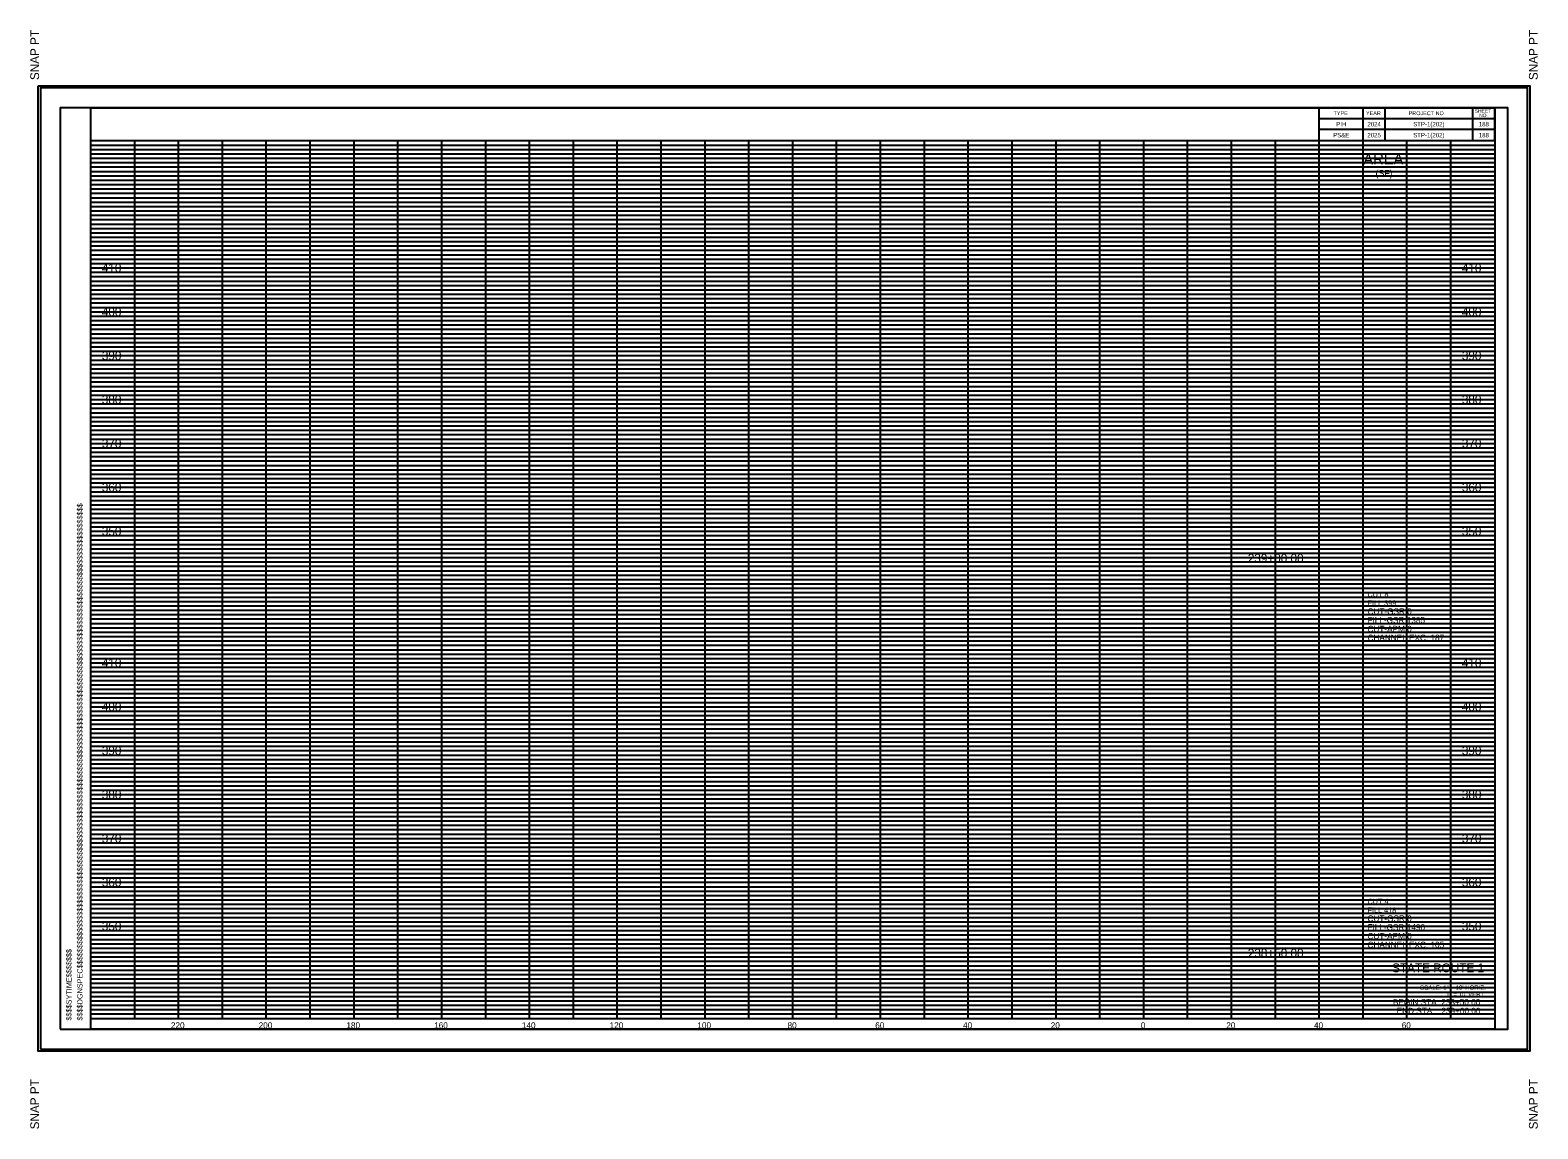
# Model space of a CAD drawing. Extents: x -200 to 23470, y -200 to 2389.
# Drawn here: x 11206.2 to 11549.8, y 974.8 to 1225.2 of the extents above; entities that cross this region are included whole.
import ezdxf

# ---------------------------------------------------------------- set-up
doc = ezdxf.new("R2010")
doc.units = 0
for name, color, linetype in [('Default', 7, 'Continuous'), ('DESIGN - SCRATCH - User 1', 7, 'Continuous'), ('DESIGN - SHEET - Corner Text', 7, 'Continuous'), ('DESIGN - SHEET - Light Grid', 7, 'Continuous'), ('DESIGN - SHEET - Linework', 7, 'Continuous'), ('DESIGN - SHEET - Plot Shape', 7, 'Continuous'), ('DESIGN - TYPICAL - Text', 7, 'Continuous')]:
    doc.layers.add(name, color=color, linetype=linetype)

# ---------------------------------------------------------------- blocks, each defined once
blk = doc.blocks.new('XSTSHT')
at = {"layer": 'DESIGN - SCRATCH - User 1'}
for p, q in [((28.5, 20.375), (28.5, 20.375)), ((29.25, 20.375), (29.25, 20.375)), ((30.5, 20.375), (30.5, 20.375)), ((31.75, 20.375), (31.75, 20.375)), ((28.5, 20.125), (28.5, 20.125)), ((29.25, 20.125), (29.25, 20.125)), ((30.5, 20.125), (30.5, 20.125)), ((31.75, 20.125), (31.75, 20.125)), ((0, 0), (0, 0))]:
    blk.add_line(p, q, dxfattribs=at)
at = {"layer": 'DESIGN - SHEET - Light Grid'}
for p, q in [((0, 19.9), (32, 19.9)), ((0, 19.8), (32, 19.8)), ((0, 19.7), (32, 19.7)), ((0, 19.6), (32, 19.6)), ((0, 19.5), (32, 19.5)), ((0, 19.4), (32, 19.4)), ((0, 19.3), (32, 19.3)), ((0, 19.2), (32, 19.2)), ((0, 19.1), (32, 19.1)), ((0, 18.9), (32, 18.9)), ((0, 18.8), (32, 18.8)), ((0, 18.7), (32, 18.7)), ((0, 18.6), (32, 18.6)), ((0, 18.5), (32, 18.5)), ((0, 18.4), (32, 18.4)), ((0, 18.3), (32, 18.3)), ((0, 18.2), (32, 18.2)), ((0, 18.1), (32, 18.1)), ((0, 17.9), (32, 17.9)), ((0, 17.8), (32, 17.8)), ((0, 17.7), (32, 17.7)), ((0, 17.6), (32, 17.6)), ((0, 17.5), (32, 17.5)), ((0, 17.4), (32, 17.4)), ((0, 17.3), (32, 17.3)), ((0, 17.2), (32, 17.2)), ((0, 17.1), (32, 17.1)), ((0, 16.9), (32, 16.9)), ((0, 16.8), (32, 16.8)), ((0, 16.7), (32, 16.7)), ((0, 16.6), (32, 16.6)), ((0, 16.5), (32, 16.5)), ((0, 16.4), (32, 16.4)), ((0, 16.3), (32, 16.3)), ((0, 16.2), (32, 16.2)), ((0, 16.1), (32, 16.1)), ((0, 15.9), (32, 15.9)), ((0, 15.8), (32, 15.8)), ((0, 15.7), (32, 15.7)), ((0, 15.6), (32, 15.6)), ((0, 15.5), (32, 15.5)), ((0, 15.4), (32, 15.4)), ((0, 15.3), (32, 15.3)), ((0, 15.2), (32, 15.2)), ((0, 15.1), (32, 15.1)), ((0, 14.9), (32, 14.9)), ((0, 14.8), (32, 14.8)), ((0, 14.7), (32, 14.7)), ((0, 14.6), (32, 14.6)), ((0, 14.5), (32, 14.5)), ((0, 14.4), (32, 14.4)), ((0, 14.3), (32, 14.3)), ((0, 14.2), (32, 14.2)), ((0, 14.1), (32, 14.1)), ((0, 13.9), (32, 13.9)), ((0, 13.8), (32, 13.8)), ((0, 13.7), (32, 13.7)), ((0, 13.6), (32, 13.6)), ((0, 13.5), (32, 13.5)), ((0, 13.4), (32, 13.4)), ((0, 13.3), (32, 13.3)), ((0, 13.2), (32, 13.2)), ((0, 13.1), (32, 13.1)), ((0, 12.9), (32, 12.9)), ((0, 12.8), (32, 12.8)), ((0, 12.7), (32, 12.7)), ((0, 12.6), (32, 12.6)), ((0, 12.5), (32, 12.5)), ((0, 12.4), (32, 12.4)), ((0, 12.3), (32, 12.3)), ((0, 12.2), (32, 12.2)), ((0, 12.1), (32, 12.1)), ((0, 11.9), (32, 11.9)), ((0, 11.8), (32, 11.8)), ((0, 11.7), (32, 11.7)), ((0, 11.6), (32, 11.6)), ((0, 11.5), (32, 11.5)), ((0, 11.4), (32, 11.4)), ((0, 11.3), (32, 11.3)), ((0, 11.2), (32, 11.2)), ((0, 11.1), (32, 11.1)), ((0, 10.9), (32, 10.9)), ((0, 10.8), (32, 10.8)), ((0, 10.7), (32, 10.7)), ((0, 10.6), (32, 10.6)), ((0, 10.5), (32, 10.5)), ((0, 10.4), (32, 10.4)), ((0, 10.3), (32, 10.3)), ((0, 10.2), (32, 10.2)), ((0, 10.1), (32, 10.1)), ((0, 9.9), (32, 9.9)), ((0, 9.8), (32, 9.8)), ((0, 9.7), (32, 9.7)), ((0, 9.6), (32, 9.6)), ((0, 9.5), (32, 9.5)), ((0, 9.4), (32, 9.4)), ((0, 9.3), (32, 9.3)), ((0, 9.2), (32, 9.2)), ((0, 9.1), (32, 9.1)), ((0, 8.9), (32, 8.9)), ((0, 8.8), (32, 8.8)), ((0, 8.7), (32, 8.7)), ((0, 8.6), (32, 8.6)), ((0, 8.5), (32, 8.5)), ((0, 8.4), (32, 8.4)), ((0, 8.3), (32, 8.3)), ((0, 8.2), (32, 8.2)), ((0, 8.1), (32, 8.1)), ((0, 7.9), (32, 7.9)), ((0, 7.8), (32, 7.8)), ((0, 7.7), (32, 7.7)), ((0, 7.6), (32, 7.6)), ((0, 7.5), (32, 7.5)), ((0, 7.4), (32, 7.4)), ((0, 7.3), (32, 7.3)), ((0, 7.2), (32, 7.2)), ((0, 7.1), (32, 7.1)), ((0, 6.9), (32, 6.9)), ((0, 6.8), (32, 6.8)), ((0, 6.7), (32, 6.7)), ((0, 6.6), (32, 6.6)), ((0, 6.5), (32, 6.5)), ((0, 6.4), (32, 6.4)), ((0, 6.3), (32, 6.3)), ((0, 6.2), (32, 6.2)), ((0, 6.1), (32, 6.1)), ((0, 5.9), (32, 5.9)), ((0, 5.8), (32, 5.8)), ((0, 5.7), (32, 5.7)), ((0, 5.6), (32, 5.6)), ((0, 5.5), (32, 5.5)), ((0, 5.4), (32, 5.4)), ((0, 5.3), (32, 5.3)), ((0, 5.2), (32, 5.2)), ((0, 5.1), (32, 5.1)), ((0, 4.9), (32, 4.9)), ((0, 4.8), (32, 4.8)), ((0, 4.7), (32, 4.7)), ((0, 4.6), (32, 4.6)), ((0, 4.5), (32, 4.5)), ((0, 4.4), (32, 4.4)), ((0, 4.3), (32, 4.3)), ((0, 4.2), (32, 4.2)), ((0, 4.1), (32, 4.1)), ((0, 3.9), (32, 3.9)), ((0, 3.8), (32, 3.8)), ((0, 3.7), (32, 3.7)), ((0, 3.6), (32, 3.6)), ((0, 3.5), (32, 3.5)), ((0, 3.4), (32, 3.4)), ((0, 3.3), (32, 3.3)), ((0, 3.2), (32, 3.2)), ((0, 3.1), (32, 3.1)), ((0, 2.9), (32, 2.9)), ((0, 2.8), (32, 2.8)), ((0, 2.7), (32, 2.7)), ((0, 2.6), (32, 2.6)), ((0, 2.5), (32, 2.5)), ((0, 2.4), (32, 2.4)), ((0, 2.3), (32, 2.3)), ((0, 2.2), (32, 2.2)), ((0, 2.1), (32, 2.1)), ((0, 1.9), (32, 1.9)), ((0, 1.8), (32, 1.8)), ((0, 1.7), (32, 1.7)), ((0, 1.6), (32, 1.6)), ((0, 1.5), (32, 1.5)), ((0, 1.4), (32, 1.4)), ((0, 1.3), (32, 1.3)), ((0, 1.2), (32, 1.2)), ((0, 1.1), (32, 1.1)), ((0, 0.9), (32, 0.9)), ((0, 0.8), (32, 0.8)), ((0, 0.7), (32, 0.7)), ((0, 0.6), (32, 0.6)), ((0, 0.5), (32, 0.5)), ((0, 0.4), (32, 0.4)), ((0, 0.3), (32, 0.3)), ((0, 0.2), (32, 0.2)), ((0, 0.1), (32, 0.1))]:
    blk.add_line(p, q, dxfattribs=at)
at = {"layer": 'DESIGN - SHEET - Linework'}
for p, q in [((32, 20.75), (28, 20.75)), ((28, 20), (28, 20.75)), ((29, 20), (29, 20.75)), ((29.5, 20), (29.5, 20.75)), ((31.5, 20), (31.5, 20.75)), ((32, 20), (32, 20.75)), ((32, 20.5), (28, 20.5)), ((0, 20), (32, 20)), ((1, 0), (1, 20)), ((2, 0), (2, 20)), ((3, 0), (3, 20)), ((4, 0), (4, 20)), ((5, 0), (5, 20)), ((6, 0), (6, 20)), ((7, 0), (7, 20)), ((8, 0), (8, 20)), ((9, 0), (9, 20)), ((10, 0), (10, 20)), ((11, 0), (11, 20)), ((12, 0), (12, 20)), ((13, 0), (13, 20)), ((14, 0), (14, 20)), ((15, 0), (15, 20)), ((16, 0), (16, 20)), ((17, 0), (17, 20)), ((18, 0), (18, 20)), ((19, 0), (19, 20)), ((20, 0), (20, 20)), ((21, 0), (21, 20)), ((22, 0), (22, 20)), ((23, 0), (23, 20)), ((24, 0), (24, 20)), ((25, 0), (25, 20)), ((26, 0), (26, 20)), ((27, 0), (27, 20)), ((32, 20.25), (28, 20.25)), ((28, 0), (28, 20)), ((29, 0), (29, 20)), ((30, 0), (30, 20)), ((31, 0), (31, 20)), ((0, 19), (32, 19)), ((0, 18), (32, 18)), ((0, 17), (32, 17)), ((0, 16), (32, 16)), ((0, 15), (32, 15)), ((0, 14), (32, 14)), ((0, 13), (32, 13)), ((0, 12), (32, 12)), ((0, 11), (32, 11)), ((0, 10), (32, 10)), ((0, 9), (32, 9)), ((0, 8), (32, 8)), ((0, 7), (32, 7)), ((0, 6), (32, 6)), ((0, 5), (32, 5)), ((0, 4), (32, 4)), ((0, 3), (32, 3)), ((0, 2), (32, 2)), ((0, 1), (32, 1)), ((0, 0), (32, 0))]:
    blk.add_line(p, q, dxfattribs=at)
for points in [[(-1.2, 21.25), (32.8, 21.25), (32.8, -0.75), (-1.2, -0.75)], [(0, 20.75), (32, 20.75), (32, -0.25), (0, -0.25)]]:
    blk.add_lwpolyline(points, close=True, dxfattribs=at)
at = {"layer": 'DESIGN - SHEET - Corner Text'}
for s, height, p in [('  SNAP PT', 0.2, (-1.18, 21.23)), ('  SNAP PT', 0.2, (32.98, 21.23)), ('$$$$DGNSPEC$$$$$$$$$$$$$$$$$$$$$$$$$$$$$$$$$$$$$$$$$$$$$$$$$$$$$$$$$$$$$$$$$$$$$$$$$$$$$$$$$$$$$$$$$$$$$$$$$$$$$$$$$$$$$$$$$$$', 0.12, (-0.19, -0.05)), ('$$$$SYTIME$$$$$$$', 0.12, (-0.44, -0.05)), ('SNAP PT  ', 0.2, (-1.18, -2.53)), ('SNAP PT  ', 0.2, (32.98, -2.53))]:
    blk.add_text(s, height=height, rotation=90, dxfattribs=at).set_placement(p)
at = {"layer": 'DESIGN - SHEET - Light Grid'}
for s, height, p in [('TYPE', 0.09, (28.326, 20.58)), ('YEAR', 0.09, (29.066, 20.58)), ('PROJECT NO.', 0.09, (30.038, 20.58)), ('SHEET', 0.08, (31.547, 20.635)), ('NO.', 0.08, (31.647, 20.535))]:
    blk.add_text(s, height=height, dxfattribs=at).set_placement(p)

msp = doc.modelspace()

# ---------------------------------------------------------------- linework, layer by layer
at = {"layer": 'DESIGN - SHEET - Plot Shape'}
for points in [[(11208.5, 993), (11547.5, 993), (11547.5, 1212), (11208.5, 1212)], [(11213, 997.5), (11543, 997.5), (11543, 1207.5), (11213, 1207.5)]]:
    msp.add_lwpolyline(points, close=True, dxfattribs=at)

# ---------------------------------------------------------------- block references
at = {"layer": 'DESIGN - SHEET - Plot Shape', "xscale": 10, "yscale": 10}
msp.add_blockref('XSTSHT', (11220, 1000), dxfattribs=at)
msp.add_blockref('XSTSHT', (11220, 1000), dxfattribs=at)
msp.add_blockref('XSTSHT', (11220, 1000), dxfattribs=at)

# ---------------------------------------------------------------- texts
at = {"layer": 'Default'}
for s, height, p in [('     410     ', 2, (11218.79, 1170)), ('     410     ', 2, (11528.79, 1170)), ('     400     ', 2, (11218.79, 1160)), ('     400     ', 2, (11528.79, 1160)), ('     390     ', 2, (11218.79, 1150)), ('     390     ', 2, (11528.79, 1150)), ('     380     ', 2, (11218.79, 1140)), ('     380     ', 2, (11528.79, 1140)), ('     370     ', 2, (11218.79, 1130)), ('     370     ', 2, (11528.79, 1130)), ('     360     ', 2, (11218.79, 1120)), ('     360     ', 2, (11528.79, 1120)), ('     350     ', 2, (11218.79, 1110)), ('     350     ', 2, (11528.79, 1110)), ('     239+00.00     ', 2, (11480, 1103.84)), ('     410     ', 2, (11218.79, 1080)), ('     410     ', 2, (11528.79, 1080)), ('     400     ', 2, (11218.79, 1070)), ('     400     ', 2, (11528.79, 1070)), ('     390     ', 2, (11218.79, 1060)), ('     390     ', 2, (11528.79, 1060)), ('     380     ', 2, (11218.79, 1050)), ('     380     ', 2, (11528.79, 1050)), ('     370     ', 2, (11218.79, 1040)), ('     370     ', 2, (11528.79, 1040)), ('     360     ', 2, (11218.79, 1030)), ('     360     ', 2, (11528.79, 1030)), ('     350     ', 2, (11218.79, 1020)), ('     350     ', 2, (11528.79, 1020)), ('     238+50.00     ', 2, (11480, 1013.86)), ('     220     ', 1.4, (11235.65, 997.7)), ('     200     ', 1.4, (11255.65, 997.7)), ('     180     ', 1.4, (11275.65, 997.7)), ('     160     ', 1.4, (11295.65, 997.7)), ('     140     ', 1.4, (11315.65, 997.7)), ('     120     ', 1.4, (11335.65, 997.7)), ('     100     ', 1.4, (11355.65, 997.7)), ('     80     ', 1.4, (11376.2, 997.7)), ('     60     ', 1.4, (11396.2, 997.7)), ('     40     ', 1.4, (11416.2, 997.7)), ('     20     ', 1.4, (11436.2, 997.7)), ('     0     ', 1.4, (11456.74, 997.7)), ('     0     ', 1.4, (11456.74, 997.7)), ('     20     ', 1.4, (11476.2, 997.7)), ('     40     ', 1.4, (11496.2, 997.7)), ('     60     ', 1.4, (11516.2, 997.7))]:
    msp.add_text(s, height=height, dxfattribs=at).set_placement(p)
at = {"layer": 'DESIGN - SHEET - Corner Text'}
for s, height, p in [('PIH', 1, (11503.89, 1203.25)), ('2024', 1, (11510.98, 1203.25)), ('STP-1(202)', 1, (11521.42, 1203.25)), ('188', 1, (11536.37, 1203.25)), ('PS&E', 1, (11503.17, 1200.75)), ('2025', 1, (11510.97, 1200.75)), ('STP-1(202)', 1, (11521.42, 1200.75)), ('188', 1, (11536.37, 1200.75)), ('STATE ROUTE 1', 2, (11516.62, 1010.5)), ('SCALE: 1" = 10\' HORIZ.', 1, (11522.96, 1006.5)), ('BEGIN STA. 238+50.00', 1.4, (11516.78, 1003)), ('1" = 10\' VERT.', 1, (11528.93, 1005)), ('END STA.   239+00.00', 1.4, (11517.65, 1001))]:
    msp.add_text(s, height=height, dxfattribs=at).set_placement(p)
at = {"layer": 'DESIGN - TYPICAL - Text'}
for s, height, p in [('AREA', 2.5, (11510.07, 1194.56)), ('(SF)', 1.5, (11512.83, 1191.81)), ('CUT 8', 1.2, (11511, 1096.04)), ('CUT-GSR 0', 1.4, (11511, 1092.04)), ('FILL 399', 1.2, (11511, 1094.04)), ('CUT-APM 0', 1.4, (11511, 1088.04)), ('FILL-GSR 1385', 1.4, (11511, 1090.04)), ('CHANNEL EXC. 187', 1.4, (11511, 1086.04)), ('CUT 4', 1.2, (11511, 1026.06)), ('FILL 418', 1.2, (11511, 1024.06)), ('CUT-GSR 0', 1.4, (11511, 1022.06)), ('FILL-GSR 1490', 1.4, (11511, 1020.06)), ('CUT-APM 0', 1.4, (11511, 1018.06)), ('CHANNEL EXC. 105', 1.4, (11511, 1016.06))]:
    msp.add_text(s, height=height, dxfattribs=at).set_placement(p)

doc.saveas('drawing.dxf')
